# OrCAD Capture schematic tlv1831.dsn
size A
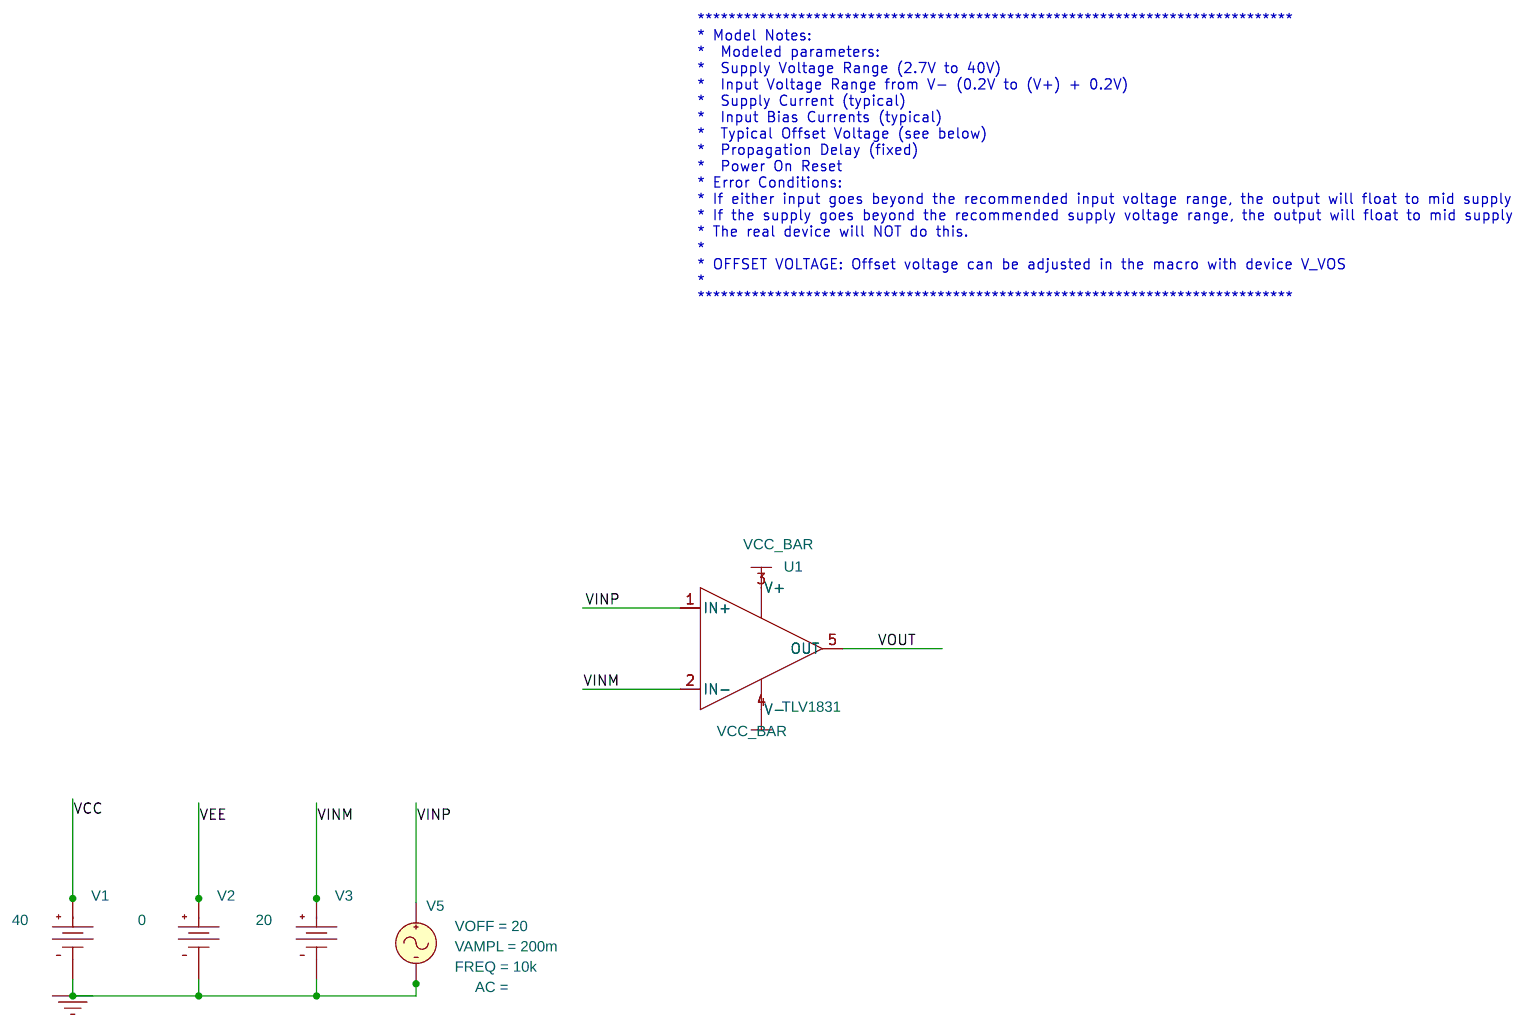
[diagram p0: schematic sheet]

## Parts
U1  TLV1831
V1  VDC
V2  VDC
V3  VDC
V5  VSIN

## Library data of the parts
U1 = TLV1831
V1 = VDC: DC: 40
V2 = VDC: DC: 0
V3 = VDC: DC: 20
V5 = VSIN: FREQ: 10k; VAMPL: 200m; VOFF: 20

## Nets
VCC: U1.3(V+) V1.0(+)
VEE: U1.4(V-) V2.0(+)
VINM: U1.2(IN-) V3.0(+)
VINP: U1.1(IN+) V5.1(+)
0: V1.1(-) V2.1(-) V3.1(-) V5.2(-)
VOUT: U1.5(OUT)

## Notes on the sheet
- *****************************************************************************
  * Model Notes:
  *  Modeled parameters:
  *  Supply Voltage Range (2.7V to 40V)
  *  Input Voltage Range from V- (0.2V to (V+) + 0.2V)
  *  Supply Current (typical)
  *  Input Bias Currents (typical)
  *  Typical Offset Voltage (see below)
  *  Propagation Delay (fixed)
  *  Power On Reset
  * Error Conditions:
  * If either input goes beyond the recommended input voltage range, the output will float to mid supply
  * If the supply goes beyond the recommended supply voltage range, the output will float to mid supply
  * The real device will NOT do this.
  *
  * OFFSET VOLTAGE: Offset voltage can be adjusted in the macro with device V_VOS
  *
  *****************************************************************************
